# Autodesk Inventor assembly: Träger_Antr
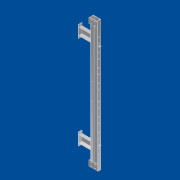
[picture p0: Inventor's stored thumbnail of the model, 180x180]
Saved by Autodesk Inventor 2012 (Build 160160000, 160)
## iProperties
Company: CAD-Verlag
Shininess: 64.0
Length Units: 11269
Angle Units: 11279
Time Units: 11290
Mass Units: 11283
Length Display Precision: 3
Angle Display Precision: 2
Compacted: True
Created: 2004-09
Part Number: Träger_Antr
Document SubType Name: Assembly
Designer: Greiling
Manufacturer: Standard
Standards Organization: Custom
Density: 0.0
Volumn: 0.0
Area: 0.0
PropertySet Name: Model Information
Control State: 0
Master: False
Checked Out: False
Author: Jürgen Kronas
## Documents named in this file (6)
- C:\DemoDaten2012\CAD Daten\Daten Vault 2012 Inventor\Kapitel 6\6.4\Rollenbahn\Rollenbahn 1400\Träger_Antr.iam
- C:\DemoDaten2012\CAD Daten\Daten Vault 2012 Inventor\Kapitel 6\6.4\Rollenbahn\Rollenbahn 1400\Träger_Antr.ipt
- C:\DemoDaten2012\CAD Daten\Daten Vault 2012 Inventor\Kapitel 6\6.4\Rollenbahn\Rollenbahn 1400\U160_247.ipt
- C:\DemoDaten2012\CAD Daten\Daten Vault 2012 Inventor\Kapitel 6\6.4\Rollenbahn\Rollenbahn 1400\Ro_spann.ipt
- C:\DemoDaten2012\CAD Daten\Daten Vault 2012 Inventor\Kapitel 6\6.4\Rollenbahn\Rollenbahn 1400\0498903.ipt
- C:\DemoDaten2012\CAD Daten\Daten Vault 2012 Inventor\Kapitel 6\6.4\Rollenbahn\Rollenbahn 1400\Fussplatte.ipt
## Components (9 placed, 5 different names)
1. Träger_Antr:1 — Passend:1, Fluchtend:1, Fluchtend:2, Passend:2, Fluchtend:3, Fluchtend:4, Fluchtend:6, Passend:3, Fluchtend:7, Passend:4, Fluchtend:8, Fluchtend:9, Passend:5, Fluchtend:10, Fluchtend:11, Fluchtend:12, Passend:6, Fluchtend:13
2. U160_247:1 — Passend:1, Fluchtend:1, Fluchtend:3, Passend:7, Passend:8, Fluchtend:14
3. U160_247:2 — Fluchtend:2, Passend:2, Fluchtend:4, Passend:9, Passend:10, Fluchtend:15
4. Ro_spann:1 — Fluchtend:6, Passend:3, Fluchtend:7
5. Ro_spann:2 — Passend:4, Fluchtend:8, Fluchtend:9
6. 0498903:1 — Passend:5, Fluchtend:10, Fluchtend:11
7. 0498903:2 — Fluchtend:12, Passend:6, Fluchtend:13
8. Fussplatte:1 — Passend:7, Passend:8, Fluchtend:14
9. Fussplatte:2 — Passend:9, Passend:10, Fluchtend:15
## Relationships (24: Flush 14, Mate 10)
- Passend:1 [Mate]: Träger_Antr:1 ↔ U160_247:1
- Fluchtend:1 [Flush]: Träger_Antr:1 ↔ U160_247:1
- Fluchtend:2 [Flush]: Träger_Antr:1 ↔ U160_247:2
- Passend:2 [Mate]: Träger_Antr:1 ↔ U160_247:2
- Fluchtend:3 [Flush]: Träger_Antr:1 ↔ U160_247:1
- Fluchtend:4 [Flush]: Träger_Antr:1 ↔ U160_247:2
- Fluchtend:6 [Flush]: Träger_Antr:1 ↔ Ro_spann:1
- Passend:3 [Mate]: Träger_Antr:1 ↔ Ro_spann:1
- Fluchtend:7 [Flush]: Träger_Antr:1 ↔ Ro_spann:1
- Passend:4 [Mate]: Träger_Antr:1 ↔ Ro_spann:2
- Fluchtend:8 [Flush]: Träger_Antr:1 ↔ Ro_spann:2
- Fluchtend:9 [Flush]: Träger_Antr:1 ↔ Ro_spann:2
- Passend:5 [Mate]: Träger_Antr:1 ↔ 0498903:1
- Fluchtend:10 [Flush]: Träger_Antr:1 ↔ 0498903:1
- Fluchtend:11 [Flush]: Träger_Antr:1 ↔ 0498903:1
- Fluchtend:12 [Flush]: Träger_Antr:1 ↔ 0498903:2
- Passend:6 [Mate]: Träger_Antr:1 ↔ 0498903:2
- Fluchtend:13 [Flush]: Träger_Antr:1 ↔ 0498903:2
- Passend:7 [Mate]: U160_247:1 ↔ Fussplatte:1
- Passend:8 [Mate]: U160_247:1 ↔ Fussplatte:1
- Fluchtend:14 [Flush]: U160_247:1 ↔ Fussplatte:1
- Passend:9 [Mate]: U160_247:2 ↔ Fussplatte:2
- Passend:10 [Mate]: U160_247:2 ↔ Fussplatte:2
- Fluchtend:15 [Flush]: U160_247:2 ↔ Fussplatte:2
